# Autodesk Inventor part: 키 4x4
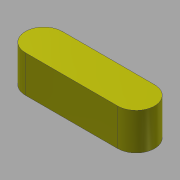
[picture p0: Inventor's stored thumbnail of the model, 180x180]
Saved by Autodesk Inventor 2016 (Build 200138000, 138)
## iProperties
Created: 2016-04
Part Number: 키 4x4
Document SubType Name: Modeling
Designer: mdu
Density: 7.86 g/cm^3
Mass: 1.65269 g
Surface Area: 2.35398 cm^2
Volume: 0.210265 cm^3
Material: 강철, 연강
Appearance: 강철 - 광택
Author: mdu
Revision Number: 1
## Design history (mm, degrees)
sketch "스케치1"
  geometry: L1 (-5, -2)-(5, -2); L2 (5, 2)-(-5, 2); A1 r 2 centre (5, 0) between (5, -2) and (5, 2); A2 r 2 centre (-5, 0) between (-5, 2) and (-5, -2); 2 further points
  constraints: 4 end point, 4 point on circle, 4 tangent, 2 centre point, 1 horizontal, 1 horizontal alignment, 1 midpoint, 1 parallel, 1 vertical alignment
  dimensions: "d0" = 4 distance between parallel lines of L1 L2; "d1" = 14 dimension on A1 A2
extrude "돌출1" new body sketch "스케치1" stored distance "d2" = 4; taper "d3" = 0 deg
node "솔리드1"
